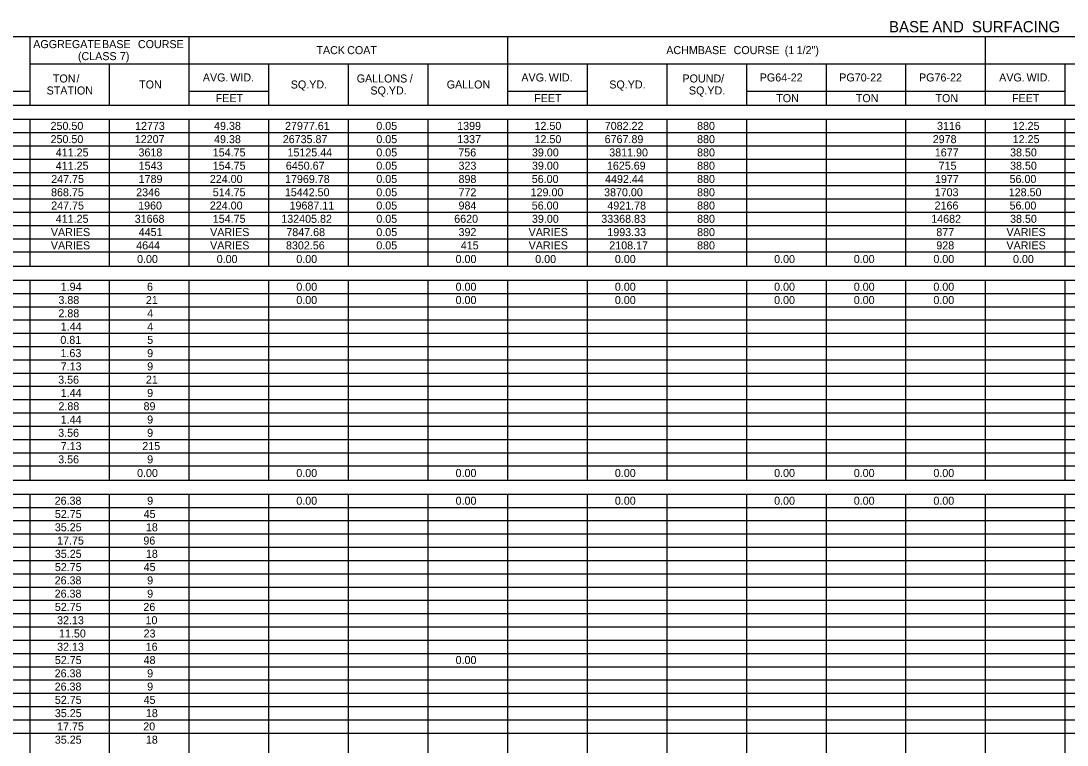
# Model space of a CAD drawing. Extents: x 1226590 to 1228573, y 151304 to 154224.
# Drawn here: x 1226976 to 1227629, y 153772 to 154224 of the extents above; entities that cross this region are included whole.
import ezdxf

# ---------------------------------------------------------------- set-up
doc = ezdxf.new("R2010")
doc.units = 0
doc.layers.add('R_Dimension', color=7, linetype='Continuous')

msp = doc.modelspace()

# ---------------------------------------------------------------- linework, layer by layer
at = {"layer": 'R_Dimension'}
for p, q in [((1226590.27, 154214.43), (1228572.93, 154214.43)), ((1226981.73, 154171.53), (1226981.73, 154214.43)), ((1227081.18, 154171.53), (1227081.18, 154214.43)), ((1227280.08, 154171.53), (1227280.08, 154214.43)), ((1227578.43, 154171.53), (1227578.43, 154214.43)), ((1226981.73, 154197.37), (1228572.93, 154197.37)), ((1227031.46, 154171.53), (1227031.46, 154197.37)), ((1227130.91, 154171.53), (1227130.91, 154197.37)), ((1227180.63, 154171.53), (1227180.63, 154197.37)), ((1227230.36, 154171.53), (1227230.36, 154197.37)), ((1227329.81, 154171.53), (1227329.81, 154197.37)), ((1227379.53, 154171.53), (1227379.53, 154197.37)), ((1227429.26, 154171.53), (1227429.26, 154197.37)), ((1227478.98, 154171.53), (1227478.98, 154197.37)), ((1227528.71, 154171.53), (1227528.71, 154197.37)), ((1227628.16, 154171.53), (1227628.16, 154197.37)), ((1226932.01, 154180.3), (1226981.73, 154180.3)), ((1227081.18, 154180.3), (1227130.91, 154180.3)), ((1227280.08, 154180.3), (1227329.81, 154180.3)), ((1227429.26, 154180.3), (1227628.16, 154180.3)), ((1226590.27, 154171.53), (1228572.93, 154171.53)), ((1226981.73, 154171.53), (1227130.91, 154171.53)), ((1227130.91, 154171.53), (1227329.81, 154171.53)), ((1227329.81, 154171.53), (1227628.16, 154171.53)), ((1227628.16, 154171.53), (1227926.51, 154171.53)), ((1226590.27, 154162.75), (1228572.93, 154162.75)), ((1226981.73, 154071.1), (1226981.73, 154162.75)), ((1227031.46, 154071.1), (1227031.46, 154162.75)), ((1227081.18, 154071.1), (1227081.18, 154162.75)), ((1227130.91, 154071.1), (1227130.91, 154162.75)), ((1227180.63, 154071.1), (1227180.63, 154162.75)), ((1227230.36, 154071.1), (1227230.36, 154162.75)), ((1227280.08, 154071.1), (1227280.08, 154162.75)), ((1227329.81, 154071.1), (1227329.81, 154162.75)), ((1227379.53, 154071.1), (1227379.53, 154162.75)), ((1227429.26, 154071.1), (1227429.26, 154162.75)), ((1227478.98, 154071.1), (1227478.98, 154162.75)), ((1227528.71, 154071.1), (1227528.71, 154162.75)), ((1227578.43, 154071.1), (1227578.43, 154162.75)), ((1227628.16, 154071.1), (1227628.16, 154162.75)), ((1226590.27, 154154.47), (1228572.93, 154154.47)), ((1226590.27, 154146.18), (1228572.93, 154146.18)), ((1226590.27, 154137.89), (1228572.93, 154137.89)), ((1226590.27, 154129.6), (1228572.93, 154129.6)), ((1226590.27, 154121.32), (1228572.93, 154121.32)), ((1226590.27, 154113.03), (1228572.93, 154113.03)), ((1226590.27, 154104.74), (1228572.93, 154104.74)), ((1226590.27, 154096.45), (1228572.93, 154096.45)), ((1226590.27, 154088.17), (1228572.93, 154088.17)), ((1226590.27, 154079.88), (1228572.93, 154079.88)), ((1226590.27, 154071.1), (1228572.93, 154071.1)), ((1226590.27, 154062.33), (1228572.93, 154062.33)), ((1226981.73, 153937.53), (1226981.73, 154062.33)), ((1227031.46, 153937.53), (1227031.46, 154062.33)), ((1227081.18, 153937.53), (1227081.18, 154062.33)), ((1227130.91, 153937.53), (1227130.91, 154062.33)), ((1227180.63, 153937.53), (1227180.63, 154062.33)), ((1227230.36, 153937.53), (1227230.36, 154062.33)), ((1227280.08, 153937.53), (1227280.08, 154062.33)), ((1227329.81, 153937.53), (1227329.81, 154062.33)), ((1227379.53, 153937.53), (1227379.53, 154062.33)), ((1227429.26, 153937.53), (1227429.26, 154062.33)), ((1227478.98, 153937.53), (1227478.98, 154062.33)), ((1227528.71, 153937.53), (1227528.71, 154062.33)), ((1227578.43, 153937.53), (1227578.43, 154062.33)), ((1227628.16, 153937.53), (1227628.16, 154062.33)), ((1226590.27, 154054.04), (1228572.93, 154054.04)), ((1226590.27, 154045.75), (1228572.93, 154045.75)), ((1226590.27, 154037.47), (1228572.93, 154037.47)), ((1226590.27, 154029.18), (1228572.93, 154029.18)), ((1226590.27, 154020.89), (1228572.93, 154020.89)), ((1226590.27, 154012.6), (1228572.93, 154012.6)), ((1226590.27, 154004.32), (1228572.93, 154004.32)), ((1226590.27, 153996.03), (1228572.93, 153996.03)), ((1226590.27, 153987.74), (1228572.93, 153987.74)), ((1226590.27, 153979.45), (1228572.93, 153979.45)), ((1226590.27, 153971.17), (1228572.93, 153971.17)), ((1226590.27, 153962.88), (1228572.93, 153962.88)), ((1226590.27, 153954.59), (1228572.93, 153954.59)), ((1226590.27, 153946.3), (1228572.93, 153946.3)), ((1226590.27, 153937.53), (1228572.93, 153937.53)), ((1226590.27, 153928.75), (1228572.93, 153928.75)), ((1226981.73, 153323.28), (1226981.73, 153928.75)), ((1227031.46, 153323.28), (1227031.46, 153928.75)), ((1227081.18, 153323.28), (1227081.18, 153928.75)), ((1227130.91, 153323.28), (1227130.91, 153928.75)), ((1227180.63, 153323.28), (1227180.63, 153928.75)), ((1227230.36, 153323.28), (1227230.36, 153928.75)), ((1227280.08, 153323.28), (1227280.08, 153928.75)), ((1227329.81, 153323.28), (1227329.81, 153928.75)), ((1227379.53, 153323.28), (1227379.53, 153928.75)), ((1227429.26, 153323.28), (1227429.26, 153928.75)), ((1227478.98, 153323.28), (1227478.98, 153928.75)), ((1227528.71, 153323.28), (1227528.71, 153928.75)), ((1227578.43, 153323.28), (1227578.43, 153928.75)), ((1227628.16, 153323.28), (1227628.16, 153928.75)), ((1226590.27, 153920.47), (1228572.93, 153920.47)), ((1226590.27, 153912.18), (1228572.93, 153912.18)), ((1226590.27, 153903.89), (1228572.93, 153903.89)), ((1226590.27, 153895.6), (1228572.93, 153895.6)), ((1226590.27, 153887.32), (1228572.93, 153887.32)), ((1226590.27, 153879.03), (1228572.93, 153879.03)), ((1226590.27, 153870.74), (1228572.93, 153870.74)), ((1226590.27, 153862.45), (1228572.93, 153862.45)), ((1226590.27, 153854.17), (1228572.93, 153854.17)), ((1226590.27, 153845.88), (1228572.93, 153845.88)), ((1226590.27, 153837.59), (1228572.93, 153837.59)), ((1226590.27, 153829.3), (1228572.93, 153829.3)), ((1226590.27, 153821.02), (1228572.93, 153821.02)), ((1226590.27, 153812.73), (1228572.93, 153812.73)), ((1226590.27, 153804.44), (1228572.93, 153804.44)), ((1226590.27, 153796.15), (1228572.93, 153796.15)), ((1226590.27, 153787.87), (1228572.93, 153787.87)), ((1226590.27, 153779.58), (1228572.93, 153779.58))]:
    msp.add_line(p, q, dxfattribs=at)

# ---------------------------------------------------------------- texts
for s, height, p in [('BASE', 7, (1227518.14, 154217.02)), (' AND', 7, (1227542.5, 154217.02)), (' SURFACING', 7, (1227567.3, 154217.02)), ('AGGREGATE', 5, (1226983.74, 154207.15)), (' BASE', 5, (1227024.84, 154207.15)), (' COURSE', 5, (1227047.25, 154207.15)), ('TACK', 5, (1227160.59, 154203.4)), (' COAT', 5, (1227177.92, 154203.4)), ('ACHM', 5, (1227379.02, 154203.4)), (' BASE', 5, (1227396.82, 154203.4)), (' COURSE', 5, (1227419.22, 154203.4)), (' (1', 5, (1227451.15, 154203.4)), (' 1/2")', 5, (1227458.59, 154203.4)), ('(CLASS', 5, (1227011.65, 154199.65)), (' 7)', 5, (1227035.99, 154199.65)), ('TON', 5, (1226996.02, 154185.7)), (' /', 5, (1227008.9, 154185.7)), ('TON', 5, (1227049.88, 154181.95)), ('AVG.', 5, (1227089.65, 154186.34)), (' WID.', 5, (1227104.92, 154186.34)), ('SQ.YD.', 5, (1227144.55, 154181.95)), ('GALLONS', 5, (1227185.73, 154185.7)), (' /', 5, (1227216.99, 154185.7)), ('GALLON', 5, (1227241.93, 154181.95)), ('AVG.', 5, (1227288.55, 154186.34)), (' WID.', 5, (1227303.82, 154186.34)), ('SQ.YD.', 5, (1227343.45, 154181.95)), ('POUND', 5, (1227389.14, 154185.7)), (' /', 5, (1227411.38, 154185.7)), ('PG', 5, (1227437.39, 154186.34)), (' 64-22', 5, (1227445.22, 154186.34)), ('PG', 5, (1227487.03, 154186.34)), (' 70-22', 5, (1227494.87, 154186.34)), ('PG', 5, (1227536.84, 154186.34)), (' 76-22', 5, (1227544.67, 154186.34)), ('AVG.', 5, (1227586.9, 154186.34)), (' WID.', 5, (1227602.17, 154186.34)), ('STATION', 5, (1226992.09, 154178.2)), ('SQ.YD.', 5, (1227194.27, 154178.2)), ('SQ.YD.', 5, (1227393.17, 154178.2)), ('FEET', 5, (1227097.68, 154173.42)), ('FEET', 5, (1227296.58, 154173.42)), ('TON', 5, (1227447.68, 154173.42)), ('TON', 5, (1227497.41, 154173.42)), ('TON', 5, (1227547.13, 154173.42)), ('FEET', 5, (1227594.93, 154173.42)), ('250.50', 5, (1226994.57, 154156.11)), ('12773', 5, (1227047.34, 154156.11)), ('49.38', 5, (1227096.68, 154156.11)), ('27977.61', 5, (1227140.97, 154156.11)), ('0.05', 5, (1227197.98, 154156.11)), ('1399', 5, (1227248.47, 154156.11)), ('12.50', 5, (1227296.78, 154156.11)), ('7082.22', 5, (1227340.62, 154156.11)), ('880', 5, (1227398.27, 154156.11)), ('3116', 5, (1227548.12, 154156.11)), ('12.25', 5, (1227595.34, 154156.11)), ('250.50', 5, (1226994.57, 154147.82)), ('12207', 5, (1227047.15, 154147.82)), ('49.38', 5, (1227096.68, 154147.82)), ('26735.87', 5, (1227139.55, 154147.82)), ('0.05', 5, (1227197.98, 154147.82)), ('1337', 5, (1227248.49, 154147.82)), ('12.50', 5, (1227296.78, 154147.82)), ('6767.89', 5, (1227340.56, 154147.82)), ('880', 5, (1227398.27, 154147.82)), ('2978', 5, (1227545.42, 154147.82)), ('12.25', 5, (1227595.34, 154147.82)), ('411.25', 5, (1226997.82, 154139.54)), ('3618', 5, (1227049.47, 154139.54)), ('154.75', 5, (1227095.85, 154139.54)), ('15125.44', 5, (1227142.5, 154139.54)), ('0.05', 5, (1227197.98, 154139.54)), ('756', 5, (1227249.18, 154139.54)), ('39.00', 5, (1227295.16, 154139.54)), ('3811.90', 5, (1227343.43, 154139.54)), ('880', 5, (1227398.27, 154139.54)), ('1677', 5, (1227546.72, 154139.54)), ('38.50', 5, (1227593.71, 154139.54)), ('411.25', 5, (1226997.82, 154131.25)), ('1543', 5, (1227049.59, 154131.25)), ('154.75', 5, (1227095.85, 154131.25)), ('6450.67', 5, (1227141.48, 154131.25)), ('0.05', 5, (1227197.98, 154131.25)), ('323', 5, (1227249.31, 154131.25)), ('39.00', 5, (1227295.16, 154131.25)), ('1625.69', 5, (1227341.97, 154131.25)), ('880', 5, (1227398.27, 154131.25)), ('715', 5, (1227549.08, 154131.25)), ('38.50', 5, (1227593.71, 154131.25)), ('247.75', 5, (1226994.98, 154122.96)), ('1789', 5, (1227049.57, 154122.96)), ('224.00', 5, (1227094.02, 154122.96)), ('17969.78', 5, (1227140.97, 154122.96)), ('0.05', 5, (1227197.98, 154122.96)), ('898', 5, (1227249.31, 154122.96)), ('56.00', 5, (1227295.04, 154122.96)), ('4492.44', 5, (1227340.81, 154122.96)), ('880', 5, (1227398.27, 154122.96)), ('1977', 5, (1227546.84, 154122.96)), ('56.00', 5, (1227593.39, 154122.96)), ('868.75', 5, (1226994.86, 154114.67)), ('2346', 5, (1227048.03, 154114.67)), ('514.75', 5, (1227095.85, 154114.67)), ('15442.50', 5, (1227140.87, 154114.67)), ('0.05', 5, (1227197.98, 154114.67)), ('772', 5, (1227249.31, 154114.67)), ('129.00', 5, (1227294.33, 154114.67)), ('3870.00', 5, (1227340.2, 154114.67)), ('880', 5, (1227398.27, 154114.67)), ('1703', 5, (1227546.64, 154114.67)), ('128.50', 5, (1227592.88, 154114.67)), ('247.75', 5, (1226994.98, 154106.39)), ('1960', 5, (1227049.25, 154106.39)), ('224.00', 5, (1227094.02, 154106.39)), ('19687.11', 5, (1227143.8, 154106.39)), ('0.05', 5, (1227197.98, 154106.39)), ('984', 5, (1227249.31, 154106.39)), ('56.00', 5, (1227295.04, 154106.39)), ('4921.78', 5, (1227342.23, 154106.39)), ('880', 5, (1227398.27, 154106.39)), ('2166', 5, (1227546.58, 154106.39)), ('56.00', 5, (1227593.39, 154106.39)), ('411.25', 5, (1226997.82, 154098.1)), ('31668', 5, (1227047.11, 154098.1)), ('154.75', 5, (1227095.85, 154098.1)), ('132405.82', 5, (1227138.64, 154098.1)), ('0.05', 5, (1227197.98, 154098.1)), ('6620', 5, (1227246.62, 154098.1)), ('39.00', 5, (1227295.16, 154098.1)), ('33368.83', 5, (1227338.45, 154098.1)), ('880', 5, (1227398.27, 154098.1)), ('14682', 5, (1227544.48, 154098.1)), ('38.50', 5, (1227593.71, 154098.1)), ('VARIES', 5, (1226994.74, 154089.81)), ('4451', 5, (1227049.59, 154089.81)), ('VARIES', 5, (1227094.19, 154089.81)), ('7847.68', 5, (1227141.79, 154089.81)), ('0.05', 5, (1227197.98, 154089.81)), ('392', 5, (1227249.31, 154089.81)), ('VARIES', 5, (1227293.09, 154089.81)), ('1993.33', 5, (1227342.23, 154089.81)), ('880', 5, (1227398.27, 154089.81)), ('877', 5, (1227547.66, 154089.81)), ('VARIES', 5, (1227591.44, 154089.81)), ('VARIES', 5, (1226994.74, 154081.52)), ('4644', 5, (1227048.05, 154081.52)), ('VARIES', 5, (1227094.19, 154081.52)), ('8302.56', 5, (1227141.58, 154081.52)), ('0.05', 5, (1227197.98, 154081.52)), ('415', 5, (1227250.73, 154081.52)), ('VARIES', 5, (1227293.09, 154081.52)), ('2108.17', 5, (1227343.45, 154081.52)), ('880', 5, (1227398.27, 154081.52)), ('928', 5, (1227547.66, 154081.52)), ('VARIES', 5, (1227591.44, 154081.52)), ('0.00', 5, (1227048.58, 154072.99)), ('0.00', 5, (1227098.31, 154072.99)), ('0.00', 5, (1227148.03, 154072.99)), ('0.00', 5, (1227247.48, 154072.99)), ('0.00', 5, (1227297.21, 154072.99)), ('0.00', 5, (1227346.93, 154072.99)), ('0.00', 5, (1227446.38, 154072.99)), ('0.00', 5, (1227496.11, 154072.99)), ('0.00', 5, (1227545.83, 154072.99)), ('0.00', 5, (1227595.56, 154072.99)), ('1.94', 5, (1227000.89, 154055.69)), ('6', 5, (1227054.77, 154055.69)), ('0.00', 5, (1227148.03, 154055.69)), ('0.00', 5, (1227247.48, 154055.69)), ('0.00', 5, (1227346.93, 154055.69)), ('0.00', 5, (1227446.38, 154055.69)), ('0.00', 5, (1227496.11, 154055.69)), ('0.00', 5, (1227545.83, 154055.69)), ('3.88', 5, (1226999.47, 154047.4)), ('21', 5, (1227054.08, 154047.4)), ('0.00', 5, (1227148.03, 154047.4)), ('0.00', 5, (1227247.48, 154047.4)), ('0.00', 5, (1227346.93, 154047.4)), ('0.00', 5, (1227446.38, 154047.4)), ('0.00', 5, (1227496.11, 154047.4)), ('0.00', 5, (1227545.83, 154047.4)), ('2.88', 5, (1226999.47, 154039.11)), ('4', 5, (1227054.9, 154039.11)), ('1.44', 5, (1227000.89, 154030.82)), ('4', 5, (1227054.9, 154030.82)), ('0.81', 5, (1227000.69, 154022.54)), ('5', 5, (1227054.9, 154022.54)), ('1.63', 5, (1227000.77, 154014.25)), ('9', 5, (1227054.88, 154014.25)), ('7.13', 5, (1227000.89, 154005.96)), ('9', 5, (1227054.88, 154005.96)), ('3.56', 5, (1226999.33, 153997.67)), ('21', 5, (1227054.08, 153997.67)), ('1.44', 5, (1227000.89, 153989.39)), ('9', 5, (1227054.88, 153989.39)), ('2.88', 5, (1226999.47, 153981.1)), ('89', 5, (1227052.64, 153981.1)), ('1.44', 5, (1227000.89, 153972.81)), ('9', 5, (1227054.88, 153972.81)), ('3.56', 5, (1226999.33, 153964.52)), ('9', 5, (1227054.88, 153964.52)), ('7.13', 5, (1227000.89, 153956.24)), ('215', 5, (1227051.83, 153956.24)), ('3.56', 5, (1226999.33, 153947.95)), ('9', 5, (1227054.88, 153947.95)), ('0.00', 5, (1227048.58, 153939.42)), ('0.00', 5, (1227148.03, 153939.42)), ('0.00', 5, (1227247.48, 153939.42)), ('0.00', 5, (1227346.93, 153939.42)), ('0.00', 5, (1227446.38, 153939.42)), ('0.00', 5, (1227496.11, 153939.42)), ('0.00', 5, (1227545.83, 153939.42)), ('26.38', 5, (1226997.11, 153922.11)), ('9', 5, (1227054.88, 153922.11)), ('0.00', 5, (1227148.03, 153922.11)), ('0.00', 5, (1227247.48, 153922.11)), ('0.00', 5, (1227346.93, 153922.11)), ('0.00', 5, (1227446.38, 153922.11)), ('0.00', 5, (1227496.11, 153922.11)), ('0.00', 5, (1227545.83, 153922.11)), ('52.75', 5, (1226997.23, 153913.82)), ('45', 5, (1227052.66, 153913.82)), ('35.25', 5, (1226997.23, 153905.54)), ('18', 5, (1227054.08, 153905.54)), ('17.75', 5, (1226998.64, 153897.25)), ('96', 5, (1227052.52, 153897.25)), ('35.25', 5, (1226997.23, 153888.96)), ('18', 5, (1227054.08, 153888.96)), ('52.75', 5, (1226997.23, 153880.67)), ('45', 5, (1227052.66, 153880.67)), ('26.38', 5, (1226997.11, 153872.39)), ('9', 5, (1227054.88, 153872.39)), ('26.38', 5, (1226997.11, 153864.1)), ('9', 5, (1227054.88, 153864.1)), ('52.75', 5, (1226997.23, 153855.81)), ('26', 5, (1227052.52, 153855.81)), ('32.13', 5, (1226998.64, 153847.52)), ('10', 5, (1227053.86, 153847.52)), ('11.50', 5, (1226999.84, 153839.24)), ('23', 5, (1227052.66, 153839.24)), ('32.13', 5, (1226998.64, 153830.95)), ('16', 5, (1227053.94, 153830.95)), ('52.75', 5, (1226997.23, 153822.66)), ('48', 5, (1227052.66, 153822.66)), ('0.00', 5, (1227247.48, 153822.66)), ('26.38', 5, (1226997.11, 153814.37)), ('9', 5, (1227054.88, 153814.37)), ('26.38', 5, (1226997.11, 153806.09)), ('9', 5, (1227054.88, 153806.09)), ('52.75', 5, (1226997.23, 153797.8)), ('45', 5, (1227052.66, 153797.8)), ('35.25', 5, (1226997.23, 153789.51)), ('18', 5, (1227054.08, 153789.51)), ('17.75', 5, (1226998.64, 153781.22)), ('20', 5, (1227052.44, 153781.22)), ('35.25', 5, (1226997.23, 153772.94)), ('18', 5, (1227054.08, 153772.94))]:
    msp.add_text(s, height=height, dxfattribs=at).set_placement(p)

doc.saveas('drawing.dxf')
